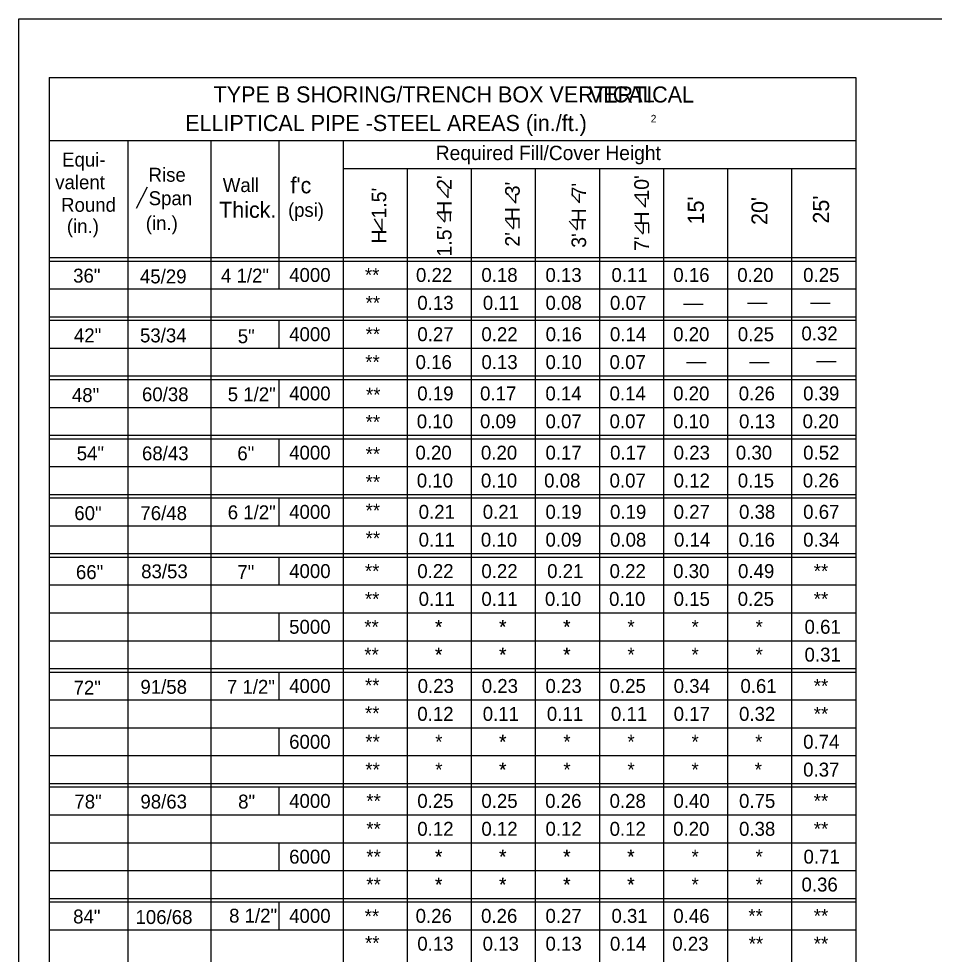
# Model space of a CAD drawing. Extents: x -22562 to -18409, y 3991 to 7171.
# Drawn here: x -19503.8 to -19322.9, y 5573.5 to 5758.4 of the extents above; entities that cross this region are included whole.
import ezdxf

# ---------------------------------------------------------------- set-up
doc = ezdxf.new("R2010")
doc.units = 0
for name, color, linetype in [('1', 7, 'Continuous'), ('2', 7, 'Continuous'), ('3', 7, 'Continuous'), ('4', 7, 'Continuous')]:
    doc.layers.add(name, color=color, linetype=linetype)

msp = doc.modelspace()

# ---------------------------------------------------------------- linework, layer by layer
at = {"layer": '1'}
for p, q in [((-19480.57, 5720.91), (-19478.38, 5725.15)), ((-19419.01, 5722.99), (-19420.57, 5724.76)), ((-19419.01, 5722.99), (-19419.01, 5724.74)), ((-19405.63, 5721.94), (-19407.2, 5723.71)), ((-19405.63, 5721.94), (-19405.63, 5723.7)), ((-19393.07, 5722), (-19394.64, 5723.77)), ((-19393.07, 5722), (-19393.07, 5723.76)), ((-19380.03, 5721.15), (-19381.59, 5722.92)), ((-19380.03, 5721.15), (-19380.03, 5722.91)), ((-19419.66, 5718.18), (-19421.23, 5719.95)), ((-19432.01, 5716.43), (-19433.57, 5718.85)), ((-19432.01, 5716.43), (-19432.01, 5718.83)), ((-19406.09, 5716.81), (-19407.65, 5718.57)), ((-19393.53, 5716.59), (-19395.09, 5718.36)), ((-19380.48, 5715.79), (-19382.04, 5717.56))]:
    msp.add_line(p, q, dxfattribs=at)
at = {"layer": '2'}
for p, q in [((-19503.85, 5194.37), (-19503.85, 5758.37)), ((-19503.85, 5758.37), (-18717.85, 5758.37)), ((-19497.85, 5746.77), (-19497.85, 5584.56)), ((-19497.85, 5746.77), (-19338.47, 5746.77)), ((-19338.47, 5746.77), (-19338.47, 5584.56)), ((-19338.47, 5741.87), (-19338.47, 5583.87)), ((-19497.85, 5734.3), (-19338.43, 5734.3)), ((-19482.27, 5734.3), (-19482.27, 5583.87)), ((-19465.89, 5734.3), (-19465.89, 5583.87)), ((-19452.43, 5734.3), (-19452.43, 5704.98)), ((-19439.77, 5734.3), (-19439.77, 5583.87)), ((-19439.77, 5728.79), (-19338.43, 5728.79)), ((-19427.1, 5728.79), (-19427.1, 5583.87)), ((-19414.44, 5728.79), (-19414.44, 5583.87)), ((-19401.78, 5728.79), (-19401.78, 5583.87)), ((-19389.12, 5728.79), (-19389.12, 5583.87)), ((-19376.46, 5728.79), (-19376.46, 5583.87)), ((-19363.79, 5728.79), (-19363.79, 5583.87)), ((-19351.13, 5728.79), (-19351.13, 5583.87)), ((-19497.85, 5711.17), (-19338.43, 5711.17)), ((-19497.85, 5710.48), (-19338.43, 5710.48)), ((-19465.89, 5710.48), (-19465.89, 5704.98)), ((-19452.43, 5710.48), (-19452.43, 5704.98)), ((-19497.85, 5704.98), (-19338.43, 5704.98)), ((-19372.49, 5701.98), (-19368.59, 5701.98)), ((-19359.85, 5702.18), (-19355.94, 5702.18)), ((-19347.39, 5702.18), (-19343.49, 5702.18)), ((-19497.85, 5699.47), (-19338.43, 5699.47)), ((-19497.85, 5699.47), (-19338.43, 5699.47)), ((-19497.85, 5698.79), (-19338.43, 5698.79)), ((-19465.89, 5698.79), (-19465.89, 5693.28)), ((-19452.43, 5698.79), (-19452.43, 5693.28)), ((-19497.85, 5693.28), (-19338.43, 5693.28)), ((-19371.91, 5690.44), (-19368, 5690.44)), ((-19359.46, 5690.44), (-19355.55, 5690.44)), ((-19346.23, 5690.63), (-19342.32, 5690.63)), ((-19497.85, 5687.78), (-19338.43, 5687.78)), ((-19497.85, 5687.78), (-19338.43, 5687.78)), ((-19497.85, 5687.09), (-19497.85, 5687.09)), ((-19497.85, 5687.09), (-19338.43, 5687.09)), ((-19465.89, 5687.09), (-19465.89, 5681.58)), ((-19452.43, 5687.09), (-19452.43, 5681.58)), ((-19497.85, 5681.58), (-19338.43, 5681.58)), ((-19497.85, 5676.08), (-19338.43, 5676.08)), ((-19497.85, 5676.08), (-19338.43, 5676.08)), ((-19497.85, 5675.39), (-19338.43, 5675.39)), ((-19465.89, 5675.39), (-19465.89, 5669.89)), ((-19452.43, 5675.39), (-19452.43, 5669.89)), ((-19497.85, 5669.89), (-19338.43, 5669.89)), ((-19497.85, 5664.38), (-19338.43, 5664.38)), ((-19497.85, 5664.38), (-19338.43, 5664.38)), ((-19497.85, 5663.69), (-19338.43, 5663.69)), ((-19465.89, 5663.69), (-19465.89, 5658.19)), ((-19452.43, 5663.69), (-19452.43, 5658.19)), ((-19497.85, 5658.19), (-19338.43, 5658.19)), ((-19497.85, 5652.68), (-19338.43, 5652.68)), ((-19497.85, 5652.68), (-19338.43, 5652.68)), ((-19497.85, 5651.99), (-19338.43, 5651.99)), ((-19465.89, 5651.99), (-19465.89, 5646.49)), ((-19452.43, 5651.99), (-19452.43, 5646.49)), ((-19497.85, 5646.49), (-19338.43, 5646.49)), ((-19497.85, 5640.98), (-19338.43, 5640.98)), ((-19465.89, 5640.98), (-19465.89, 5635.48)), ((-19452.43, 5640.98), (-19452.43, 5635.48)), ((-19497.85, 5635.48), (-19338.43, 5635.48)), ((-19497.85, 5629.97), (-19338.43, 5629.97)), ((-19497.85, 5629.97), (-19338.43, 5629.97)), ((-19497.85, 5629.29), (-19338.43, 5629.29)), ((-19465.89, 5629.29), (-19465.89, 5623.78)), ((-19452.43, 5629.29), (-19452.43, 5623.78)), ((-19497.85, 5623.78), (-19338.43, 5623.78)), ((-19497.85, 5618.28), (-19338.43, 5618.28)), ((-19465.89, 5618.28), (-19465.89, 5612.77)), ((-19465.89, 5618.28), (-19465.89, 5612.77)), ((-19452.43, 5618.28), (-19452.43, 5612.77)), ((-19497.85, 5612.77), (-19338.43, 5612.77)), ((-19497.85, 5607.27), (-19338.43, 5607.27)), ((-19497.85, 5607.27), (-19338.43, 5607.27)), ((-19497.85, 5606.58), (-19338.43, 5606.58)), ((-19465.89, 5606.58), (-19465.89, 5601.07)), ((-19452.43, 5606.58), (-19452.43, 5601.07)), ((-19497.85, 5601.07), (-19338.43, 5601.07)), ((-19497.85, 5595.57), (-19338.43, 5595.57)), ((-19465.89, 5595.57), (-19465.89, 5590.06)), ((-19465.89, 5595.57), (-19465.89, 5590.06)), ((-19452.43, 5595.57), (-19452.43, 5590.06)), ((-19497.85, 5590.06), (-19338.43, 5590.06)), ((-19497.85, 5584.56), (-19497.85, 5414.6)), ((-19497.85, 5584.56), (-19338.47, 5584.56)), ((-19497.85, 5584.56), (-19338.47, 5584.56)), ((-19338.47, 5584.56), (-19338.47, 5414.6)), ((-19497.85, 5583.87), (-19338.43, 5583.87)), ((-19482.27, 5583.87), (-19482.27, 5414.6)), ((-19465.89, 5583.87), (-19465.89, 5578.37)), ((-19465.89, 5583.87), (-19465.89, 5415.29)), ((-19452.43, 5583.87), (-19452.43, 5578.37)), ((-19452.43, 5583.87), (-19452.43, 5578.37)), ((-19439.77, 5583.87), (-19439.77, 5414.6)), ((-19427.1, 5583.87), (-19427.1, 5415.29)), ((-19414.44, 5583.87), (-19414.44, 5415.29)), ((-19401.78, 5583.87), (-19401.78, 5414.6)), ((-19389.12, 5583.87), (-19389.12, 5415.29)), ((-19376.46, 5583.87), (-19376.46, 5414.6)), ((-19363.79, 5583.87), (-19363.79, 5414.6)), ((-19351.13, 5583.87), (-19351.13, 5414.6)), ((-19338.47, 5583.87), (-19338.47, 5415.29)), ((-19497.85, 5578.37), (-19338.43, 5578.37))]:
    msp.add_line(p, q, dxfattribs=at)

# ---------------------------------------------------------------- texts
at = {"layer": '1'}
for s, height, p in [('VERTICAL', 3.178, (-19391.2, 5741.81)), ('Equi-', 2.751, (-19495.27, 5729.16)), ('Rise', 2.751, (-19478.19, 5726.16)), ('valent', 2.751, (-19496.63, 5724.69)), ('Wall', 2.751, (-19463.53, 5724.12)), ("f'c", 3.172, (-19450.14, 5723.87)), ('Round', 2.751, (-19495.47, 5720.22)), ('Span', 2.751, (-19478.17, 5721.53)), ('Thick.', 3.172, (-19464.24, 5719.03)), ('(psi)', 2.719, (-19450.62, 5719.23)), ('(in.)', 2.751, (-19478.74, 5716.6)), ('(in.)', 2.751, (-19494.33, 5716)), ('36"', 2.751, (-19493.09, 5706.23)), ('45/29', 2.751, (-19479.89, 5706.08)), ('4 1/2"', 2.751, (-19463.88, 5706.23)), ('42"', 2.751, (-19492.93, 5694.42)), ('53/34', 2.751, (-19479.88, 5694.42)), ('5"', 2.751, (-19460.57, 5694.26)), ('60/38', 2.751, (-19479.49, 5682.78)), ('5 1/2"', 2.751, (-19462.55, 5682.78)), ('48"', 2.751, (-19493.33, 5682.63)), ('54"', 2.751, (-19492.39, 5671.12)), ('68/43', 2.751, (-19479.49, 5671.12)), ('6"', 2.751, (-19460.65, 5671.12)), ('60"', 2.751, (-19492.86, 5659.31)), ('76/48', 2.751, (-19479.8, 5659.31)), ('6 1/2"', 2.751, (-19462.55, 5659.47)), ('83/53', 2.751, (-19479.65, 5647.81)), ('66"', 2.751, (-19492.54, 5647.66)), ('7"', 2.751, (-19460.65, 5647.66)), ('72"', 2.751, (-19493.01, 5624.83)), ('91/58', 2.751, (-19479.8, 5624.99)), ('7 1/2"', 2.751, (-19462.71, 5624.99)), ('78"', 2.751, (-19492.85, 5602.32)), ('98/63', 2.751, (-19479.8, 5602.32)), ('8"', 2.751, (-19460.49, 5602.32)), ('84"', 2.751, (-19493.09, 5579.62)), ('106/68', 2.751, (-19480.77, 5579.51)), ('8 1/2"', 2.751, (-19462.28, 5579.78))]:
    msp.add_text(s, height=height, dxfattribs=at).set_placement(p)
for p in [(-19417.72, 5718.15), (-19404.14, 5716.78), (-19391.58, 5716.56), (-19378.53, 5715.76)]:
    msp.add_text('=', height=2.88, rotation=90, dxfattribs=at).set_placement(p)
at = {"layer": '2'}
for s, height, p in [('2', 1.5, (-19378.97, 5737.87)), ('Required Fill/Cover Height', 2.8357, (-19421.44, 5730.44))]:
    msp.add_text(s, height=height, dxfattribs=at).set_placement(p)
at = {"layer": '3'}
for s, height, rotation, p in [("15'", 3.172, 90, (-19368.47, 5717.73)), ("20'", 3.172, 90, (-19355.9, 5717.62)), ("25'", 3.172, 90, (-19343.74, 5717.9)), ('0.11', 2.751, 0.113, (-19386.73, 5706.35)), ('0.14', 2.751, 0.113, (-19399.77, 5682.95)), ('0.10', 2.751, 0.113, (-19425.19, 5677.44)), ('0.13', 2.751, 0.113, (-19361.52, 5677.44)), ('0.26', 2.751, 0.113, (-19348.92, 5665.75)), ('0.08', 2.751, 0.113, (-19387, 5654.05)), ('0.16', 2.751, 0.113, (-19361.59, 5654.05))]:
    msp.add_text(s, height=height, rotation=rotation, dxfattribs=at).set_placement(p)
for s, height, p in [('**', 2.753, (-19435.44, 5706.36)), ('0.22', 2.753, (-19425.35, 5706.36)), ('0.18', 2.753, (-19412.43, 5706.36)), ('0.13', 2.751, (-19399.77, 5706.36)), ('0.16', 2.753, (-19374.51, 5706.36)), ('0.20', 2.753, (-19361.87, 5706.36)), ('0.25', 2.753, (-19348.85, 5706.36)), ('**', 2.753, (-19435.3, 5700.86)), ('0.13', 2.753, (-19425.09, 5700.85)), ('0.11', 2.753, (-19412.14, 5700.85)), ('0.08', 2.753, (-19399.76, 5700.85)), ('0.07', 2.753, (-19387.03, 5700.85)), ('**', 2.753, (-19435.3, 5694.67)), ('0.27', 2.753, (-19425.08, 5694.66)), ('0.22', 2.753, (-19412.43, 5694.66)), ('0.16', 2.753, (-19399.73, 5694.66)), ('0.14', 2.753, (-19387.03, 5694.66)), ('0.20', 2.753, (-19374.54, 5694.66)), ('0.25', 2.753, (-19361.77, 5694.66)), ('0.32', 2.753, (-19349.2, 5694.81)), ('**', 2.753, (-19435.37, 5689.16)), ('0.16', 2.751, (-19425.43, 5689.15)), ('0.13', 2.753, (-19412.42, 5689.15)), ('0.10', 2.753, (-19399.76, 5689.15)), ('0.07', 2.753, (-19387.1, 5689.15)), ('0.19', 2.753, (-19425.1, 5682.96)), ('0.17', 2.753, (-19412.69, 5682.96)), ('0.14', 2.753, (-19387.1, 5682.96)), ('0.20', 2.753, (-19374.54, 5682.96)), ('0.26', 2.753, (-19361.58, 5682.96)), ('0.39', 2.753, (-19348.86, 5682.96)), ('**', 2.753, (-19435.23, 5682.7)), ('0.09', 2.753, (-19412.7, 5677.45)), ('0.07', 2.753, (-19399.76, 5677.45)), ('0.07', 2.753, (-19387.1, 5677.45)), ('0.10', 2.753, (-19374.54, 5677.45)), ('0.20', 2.753, (-19348.96, 5677.45)), ('**', 2.753, (-19435.3, 5677.33)), ('**', 2.753, (-19435.3, 5670.99)), ('0.20', 2.753, (-19425.46, 5671.26)), ('0.20', 2.753, (-19412.52, 5671.26)), ('0.17', 2.753, (-19399.76, 5671.26)), ('0.17', 2.753, (-19387, 5671.26)), ('0.23', 2.753, (-19374.44, 5671.26)), ('0.30', 2.753, (-19362.15, 5671.26)), ('0.52', 2.753, (-19348.85, 5671.26)), ('**', 2.753, (-19435.3, 5665.48)), ('0.10', 2.753, (-19425.19, 5665.75)), ('0.10', 2.753, (-19412.52, 5665.75)), ('0.08', 2.753, (-19400.03, 5665.75)), ('0.07', 2.753, (-19387.1, 5665.75)), ('0.12', 2.751, (-19374.44, 5665.75)), ('0.15', 2.753, (-19361.77, 5665.75)), ('**', 2.753, (-19435.3, 5659.83)), ('0.21', 2.753, (-19424.82, 5659.56)), ('0.21', 2.753, (-19412.16, 5659.56)), ('0.19', 2.753, (-19399.77, 5659.56)), ('0.19', 2.753, (-19387.01, 5659.56)), ('0.27', 2.753, (-19374.44, 5659.56)), ('0.38', 2.753, (-19361.52, 5659.56)), ('0.67', 2.753, (-19348.85, 5659.56)), ('**', 2.753, (-19435.3, 5654.33)), ('0.11', 2.753, (-19424.82, 5654.06)), ('0.10', 2.753, (-19412.53, 5654.06)), ('0.09', 2.753, (-19399.77, 5654.06)), ('0.14', 2.753, (-19374.37, 5654.06)), ('0.34', 2.753, (-19348.85, 5654.06)), ('**', 2.753, (-19435.44, 5647.86)), ('0.22', 2.753, (-19425.09, 5647.86)), ('0.22', 2.753, (-19412.43, 5647.86)), ('0.21', 2.753, (-19399.43, 5647.86)), ('0.22', 2.753, (-19387.1, 5647.86)), ('0.30', 2.753, (-19374.54, 5647.86)), ('0.49', 2.753, (-19361.72, 5647.86)), ('**', 2.753, (-19346.76, 5647.86)), ('**', 2.753, (-19435.44, 5642.35)), ('0.11', 2.753, (-19424.82, 5642.36)), ('0.11', 2.753, (-19412.43, 5642.36)), ('0.10', 2.753, (-19399.87, 5642.36)), ('0.10', 2.753, (-19387.2, 5642.36)), ('0.15', 2.753, (-19374.44, 5642.36)), ('0.25', 2.753, (-19361.78, 5642.36)), ('**', 2.753, (-19346.76, 5642.36)), ('**', 2.753, (-19435.56, 5636.85)), ('*', 2.75, (-19421.62, 5636.85)), ('*', 2.75, (-19421.55, 5636.85)), ('*', 2.75, (-19408.96, 5636.85)), ('*', 2.75, (-19408.89, 5636.85)), ('*', 2.75, (-19396.3, 5636.85)), ('*', 2.75, (-19396.23, 5636.85)), ('*', 2.75, (-19383.57, 5636.85)), ('*', 2.75, (-19370.91, 5636.85)), ('*', 2.75, (-19358.25, 5636.85)), ('0.61', 2.753, (-19348.58, 5636.85)), ('**', 2.753, (-19435.56, 5631.34)), ('*', 2.75, (-19421.62, 5631.35)), ('*', 2.75, (-19421.55, 5631.35)), ('*', 2.75, (-19408.96, 5631.35)), ('*', 2.75, (-19408.89, 5631.35)), ('*', 2.75, (-19396.3, 5631.35)), ('*', 2.75, (-19396.23, 5631.35)), ('*', 2.75, (-19383.57, 5631.35)), ('*', 2.75, (-19370.91, 5631.35)), ('*', 2.75, (-19358.25, 5631.35)), ('0.31', 2.753, (-19348.58, 5631.35)), ('**', 2.753, (-19435.43, 5625.28)), ('0.23', 2.753, (-19425.02, 5625.16)), ('0.23', 2.753, (-19412.36, 5625.16)), ('0.23', 2.753, (-19399.76, 5625.16)), ('0.25', 2.753, (-19387.1, 5625.16)), ('0.34', 2.753, (-19374.44, 5625.16)), ('0.61', 2.753, (-19361.25, 5625.16)), ('**', 2.753, (-19346.76, 5625.16)), ('**', 2.753, (-19435.43, 5619.78)), ('0.12', 2.753, (-19425.09, 5619.65)), ('0.11', 2.753, (-19412.16, 5619.65)), ('0.11', 2.753, (-19399.49, 5619.65)), ('0.11', 2.753, (-19386.83, 5619.65)), ('0.17', 2.753, (-19374.44, 5619.65)), ('0.32', 2.753, (-19361.52, 5619.65)), ('**', 2.753, (-19346.76, 5619.65)), ('**', 2.753, (-19435.36, 5614.14)), ('*', 2.75, (-19421.55, 5614.14)), ('*', 2.75, (-19408.96, 5614.14)), ('*', 2.75, (-19408.89, 5614.14)), ('*', 2.75, (-19396.23, 5614.14)), ('*', 2.75, (-19383.57, 5614.14)), ('*', 2.75, (-19370.91, 5614.14)), ('*', 2.75, (-19358.33, 5614.14)), ('0.74', 2.753, (-19348.85, 5614.14)), ('**', 2.753, (-19435.36, 5608.64)), ('*', 2.75, (-19421.55, 5608.64)), ('*', 2.75, (-19408.96, 5608.64)), ('*', 2.75, (-19408.89, 5608.64)), ('*', 2.75, (-19396.23, 5608.64)), ('*', 2.75, (-19383.57, 5608.64)), ('*', 2.75, (-19370.91, 5608.64)), ('*', 2.75, (-19358.43, 5608.64)), ('0.37', 2.753, (-19348.85, 5608.64)), ('**', 2.753, (-19435.16, 5602.44)), ('0.25', 2.753, (-19425.09, 5602.45)), ('0.25', 2.753, (-19412.43, 5602.45)), ('0.26', 2.753, (-19399.82, 5602.45)), ('0.28', 2.753, (-19387.1, 5602.45)), ('0.40', 2.753, (-19374.48, 5602.45)), ('0.75', 2.753, (-19361.52, 5602.45)), ('**', 2.753, (-19346.76, 5602.45)), ('**', 2.753, (-19435.16, 5596.94)), ('0.12', 2.753, (-19425.09, 5596.94)), ('0.12', 2.753, (-19412.43, 5596.94)), ('0.12', 2.753, (-19399.76, 5596.94)), ('0.12', 2.753, (-19387.09, 5596.94)), ('0.20', 2.753, (-19374.54, 5596.94)), ('0.38', 2.753, (-19361.52, 5596.94)), ('**', 2.753, (-19346.76, 5596.94)), ('**', 2.753, (-19435.16, 5591.43)), ('*', 2.75, (-19421.62, 5591.44)), ('*', 2.75, (-19421.55, 5591.44)), ('*', 2.75, (-19408.96, 5591.44)), ('*', 2.75, (-19408.89, 5591.44)), ('*', 2.75, (-19396.3, 5591.44)), ('*', 2.75, (-19396.23, 5591.44)), ('*', 2.75, (-19383.64, 5591.44)), ('*', 2.75, (-19383.57, 5591.44)), ('*', 2.75, (-19370.91, 5591.44)), ('*', 2.75, (-19358.25, 5591.44)), ('0.71', 2.753, (-19348.78, 5591.44)), ('**', 2.753, (-19435.16, 5585.93)), ('*', 2.75, (-19421.62, 5585.93)), ('*', 2.75, (-19421.55, 5585.93)), ('*', 2.75, (-19408.96, 5585.93)), ('*', 2.75, (-19408.89, 5585.93)), ('*', 2.75, (-19396.3, 5585.93)), ('*', 2.75, (-19396.23, 5585.93)), ('*', 2.75, (-19383.64, 5585.93)), ('*', 2.75, (-19383.57, 5585.93)), ('*', 2.75, (-19370.91, 5585.93)), ('*', 2.75, (-19358.25, 5585.93)), ('0.36', 2.753, (-19349.18, 5585.93)), ('**', 2.753, (-19435.49, 5579.68)), ('0.26', 2.753, (-19425.42, 5579.74)), ('0.26', 2.753, (-19412.49, 5579.74)), ('0.27', 2.753, (-19399.76, 5579.74)), ('0.31', 2.753, (-19386.73, 5579.74)), ('0.46', 2.753, (-19374.51, 5579.74)), ('**', 2.753, (-19359.68, 5579.74)), ('**', 2.753, (-19346.76, 5579.74)), ('**', 2.753, (-19435.42, 5574.38)), ('0.13', 2.753, (-19425.09, 5574.24)), ('0.13', 2.753, (-19412.18, 5574.24)), ('0.13', 2.753, (-19399.76, 5574.24)), ('0.14', 2.753, (-19387.03, 5574.24)), ('0.23', 2.753, (-19374.71, 5574.24)), ('**', 2.753, (-19359.62, 5574.24)), ('**', 2.753, (-19346.76, 5574.24))]:
    msp.add_text(s, height=height, dxfattribs=at).set_placement(p)
at = {"layer": '4'}
for s, height, p in [('TYPE B SHORING/TRENCH BOX VERTICAL', 3.1784, (-19465.34, 5741.82)), ('ELLIPTICAL PIPE -STEEL AREAS (in./ft.)', 3.1784, (-19470.96, 5736.17)), ('4000', 2.753, (-19450.41, 5706.36)), ('4000', 2.753, (-19450.41, 5694.66)), ('4000', 2.753, (-19450.41, 5682.96)), ('4000', 2.753, (-19450.41, 5671.26)), ('4000', 2.753, (-19450.41, 5659.56)), ('4000', 2.753, (-19450.41, 5647.86)), ('5000', 2.753, (-19450.41, 5636.85)), ('4000', 2.753, (-19450.41, 5625.16)), ('6000', 2.753, (-19450.41, 5614.14)), ('4000', 2.753, (-19450.41, 5602.45)), ('6000', 2.753, (-19450.41, 5591.44)), ('4000', 2.753, (-19450.41, 5579.74))]:
    msp.add_text(s, height=height, dxfattribs=at).set_placement(p)
for s, height, p in [("1.5'  H  2'", 2.8834, (-19418.33, 5711.37)), ("7'  H  10'", 2.883, (-19379.34, 5712.47)), ("H  1.5'", 2.883, (-19431.22, 5713.95)), ("2'  H  3'", 2.883, (-19404.85, 5713.33)), ("3'  H  7'", 2.883, (-19391.74, 5713.11))]:
    msp.add_text(s, height=height, rotation=90, dxfattribs=at).set_placement(p)

doc.saveas('drawing.dxf')
